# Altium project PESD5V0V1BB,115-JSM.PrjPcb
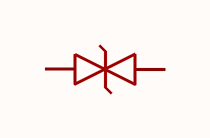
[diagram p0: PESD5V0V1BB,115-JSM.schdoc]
1 sheet, 1 parts. Net scope: global (net labels, ports and power ports of the same name join across sheets).

## Sheet PESD5V0V1BB,115-JSM.schdoc
size 127 x 101 mm

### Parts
D?  pesd5v0v1bb,115-jsm  [SOD-523_L1.2-W0.8-LS1.6-BI]  (value not drawn)

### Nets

Not connected (* = marked no-connect by the designer): D? 1 2

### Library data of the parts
D? = pesd5v0v1bb,115-jsm: 极性:-;反向截止电压(Vrwm):5V;钳位电压:15V;峰值脉冲电流(Ipp):8A@8/20us;峰值脉冲功率(Ppp):90W@8/20us;击穿电压(VBR):6V;; Manufacturer: JSMSEMI(杰盛微); AddInBom: yes; ModelId: bfbc20aaa9964d25bc07bd43d1c87046; ModelTransform: 62.992,31.496,0,0,0,0,0,0,0; Reverse Stand-Off Voltage (Vrwm): 5V; Clamping Voltage: 15V; Voltage - Breakdown: 6V; Reverse Leakage Current (Ir): 200nA; level of protection: IEC 61000-4-4；IEC 61000-4-5；IEC 61000-4-2; Type: ESD; Junction Capacitance: 23pF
